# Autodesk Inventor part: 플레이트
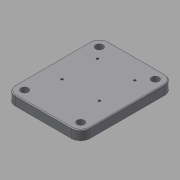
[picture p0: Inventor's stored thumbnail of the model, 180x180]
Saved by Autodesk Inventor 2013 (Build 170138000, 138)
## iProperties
Created: 2017-10
Part Number: 플레이트
Material: 일반
Document SubType Name: Modeling
Designer: mduedu
Density: 1 g/cm^3
Author: mduedu
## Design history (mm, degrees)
sketch "스케치1"
  geometry: L1 (50, 40)-(-50, 40); L2 (-50, 40)-(-50, -40); L3 (-50, -40)-(50, -40); L4 (50, -40)-(50, 40); L5 (50, 40)-(-50, -40); L6 (-50, 40)-(50, -40); 1 further point
  constraints: 12 end point, 2 midpoint, 2 parallel, 1 horizontal, 1 perpendicular
  dimensions: "d0" = 100 distance of L3.end L2.end; "d1" = 80 distance of L2.end L1.end
extrude "돌출1" new body sketch "스케치1" distance "d2" = 10; taper "d3" = 0 deg
fillet "모깎기1" dims "d4" = 10
sketch "스케치2"
  geometry: L1 (40, 40)-(-40, 40) reference; L2 (-50, 30)-(-50, -30) reference; L3 (-40, -40)-(40, -40) reference; L4 (50, -30)-(50, 30) reference; L5 (-50, 0)-(50, 0); A1 r 10 centre (40, 30) between (50, 30) and (40, 40) reference; A2 r 10 centre (-40, 30) between (-40, 40) and (-50, 30) reference; A3 r 10 centre (-40, -30) between (-50, -30) and (-40, -40) reference; A4 r 10 centre (40, -30) between (40, -40) and (50, -30) reference; 4 further points
  constraints: 2 end point, 2 midpoint, 2 symmetric about line, 1 horizontal alignment
  dimensions: "d12" = 22 distance from line of point (28, 20) L4; "d13" = 38 distance of point (-10, 20) point (28, 20); "d14" = 20 distance from line of point (28, 20) L5
hole "구멍1" sketch "스케치2" at (-10, 20), (28, 20), (28, -20), (-10, -20) diameter "d5" = 2.459; stored, may be unused: countersink angle "d9" = 90 deg, drill point angle "d11" = 120 deg; dims "d6" = 12.312, "d7" = 4, "d8" = 2, "d10" = 13.812
fillet "모깎기2" dims "d15" = 1
sketch "스케치3"
  geometry: C1 r 4 at (-40, 30); C2 r 4 at (40, 30); C3 r 4 at (40, -30); C4 r 4 at (-40, -30); A1 r 10 centre (-40, 30) between (-40, 40) and (-50, 30) reference; A2 r 10 centre (40, 30) between (50, 30) and (40, 40) reference; A3 r 10 centre (40, -30) between (40, -40) and (50, -30) reference; A4 r 10 centre (-40, -30) between (-50, -30) and (-40, -40) reference; 1 further point
  constraints: 4 centre point, 4 coincident, 3 equal radius
  dimensions: "d16" = 8 diameter of C1
extrude "돌출2" cut sketch "스케치3" stored distance "d17" = 10; taper "d18" = 0 deg
node "솔리드1"
node "투영된 루프1"
